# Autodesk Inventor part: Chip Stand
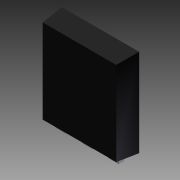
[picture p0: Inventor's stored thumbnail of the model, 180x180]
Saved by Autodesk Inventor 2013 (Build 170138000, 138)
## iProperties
Company: Autodesk Inc.
Created: 2005-12
Part Number: Chip Stand
Document SubType Name: Modeling
Designer: Autodesk Inc.
Density: 1 g/cm^3
Mass: 0.1184 g
Surface Area: 1.85413 cm^2
Volume: 0.1184 cm^3
Material: Allgemein
Title: Personal Computer
Author: Autodesk Inc.
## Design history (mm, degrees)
sketch "Sketch2"
  geometry: L1 (0, -0.2)-(0, 1.2) reference; L2 (-4.2, 0)-(4.2, 0) reference; L3 (-0.5, 0)-(0.5, 0); L4 (0.5, 0)-(0.5, 1); L5 (0.5, 1)-(-0.5, 1); L6 (-0.5, 1)-(-0.5, 0); L7 (2, 0)-(3, 0); L8 (3, 0)-(3, 1); L9 (3, 1)-(2, 1); L10 (2, 1)-(2, 0); L11 (-2, 0)-(-3, 0); L12 (-3, 0)-(-3, 1); L13 (-3, 1)-(-2, 1); L14 (-2, 1)-(-2, 0)
  constraints: 24 end point, 6 parallel, 4 equal length, 3 horizontal, 3 perpendicular, 3 point on line, 2 other
  dimensions: "d0" = 6 distance between parallel lines of L12 L8; "d1" = 1 distance of L12.end L13.end; "d2" = 1 distance of L11.end L12.end
extrude "Extrusion1" new body sketch "Sketch2" stored distance "d3" = 0.5; taper "d4" = 0 deg
sketch "Sketch3"
  geometry: L1 (0, -1.76)-(0, 10.56) reference; L2 (-0.5, 1)-(0.5, 1) reference; L3 (-3.5, 8.8)-(3.5, 8.8); L4 (3.5, 8.8)-(3.5, 0.8); L5 (3.5, 0.8)-(-3.5, 0.8); L6 (-3.5, 0.8)-(-3.5, 8.8); 1 further point
  constraints: 8 end point, 2 parallel, 1 horizontal, 1 perpendicular, 1 other
  dimensions: "d5" = 0.2 distance between parallel lines of L2 L5; "d6" = 8 distance of L5.end L3.start; "d7" = 7 distance of L3.start L3.end
extrude "Extrusion2" join sketch "Sketch3" stored distance "d8" = 2; taper "d9" = 0 deg
feature "FaceDraft1" dims angle "d10" = 5 deg
body "Solid1"
